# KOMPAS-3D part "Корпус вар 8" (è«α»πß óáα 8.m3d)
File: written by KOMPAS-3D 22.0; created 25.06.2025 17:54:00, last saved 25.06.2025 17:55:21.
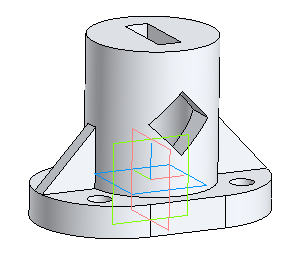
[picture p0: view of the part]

Document properties: Автор: Helen; Полное имя файла: D:\MY\WORK\MPEI\ППЭ_2025-2026\Варианты\Вар 8 СБ\Корпус вар 8.m3d

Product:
- Part/product: Корпус вар 8
    Масса: 3.880901

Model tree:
1. Операция без истории:1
